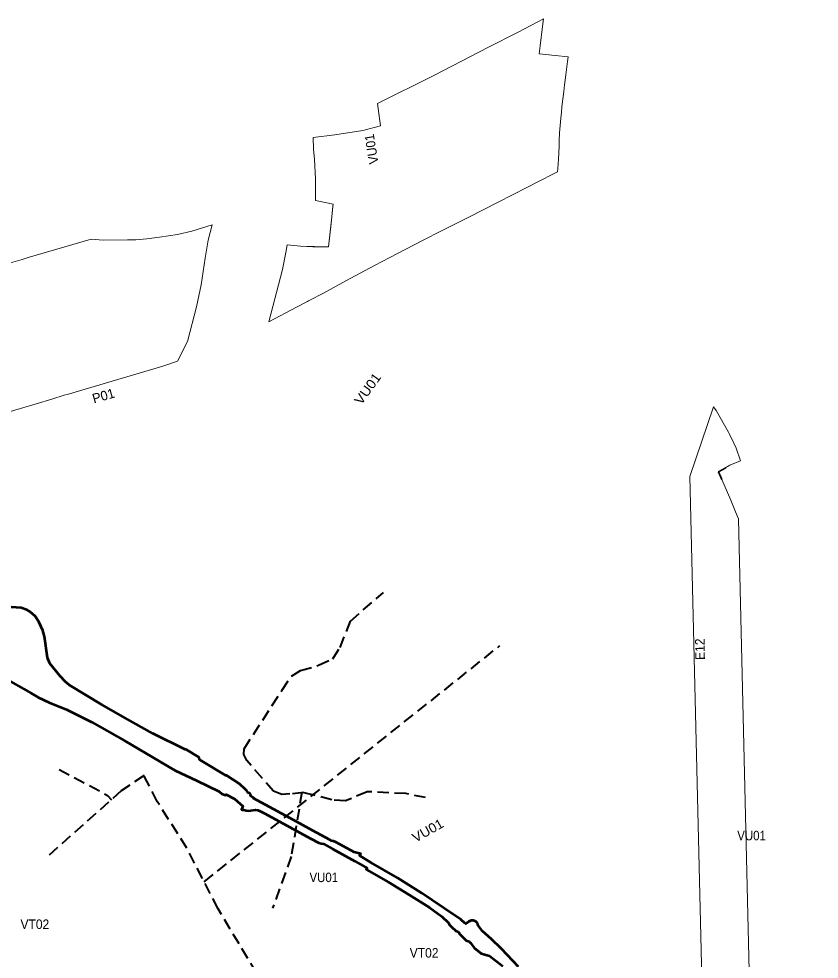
# Model space of a CAD drawing. Extents: x -650145 to -642675, y -1074338 to -1066724.
# Drawn here: x -646512 to -644824, y -1069249 to -1067267 of the extents above; entities that cross this region are included whole.
import ezdxf

# ---------------------------------------------------------------- set-up
doc = ezdxf.new("R2010")
doc.units = 0
doc.header["$LTSCALE"] = 8
doc.linetypes.add('MEDIUM_DASHED', pattern=[4.5, 3, -1.5])
for name, color, linetype, lineweight in [('12', 7, 'MEDIUM_DASHED', 40), ('15', 7, 'Continuous', 13), ('45', 7, 'Continuous', 53)]:
    doc.layers.add(name, color=color, linetype=linetype, lineweight=lineweight)
doc.layers.add('17', color=7, linetype='Continuous')
doc.layers.add('2', color=7, linetype='Continuous')

msp = doc.modelspace()

# ---------------------------------------------------------------- linework, layer by layer
at = {"layer": '12'}
msp.add_line((-646121.289, -1069086.031), (-645497.437, -1068588.325), dxfattribs=at)
for points in [[(-645654.382, -1068908.587), (-645695.934, -1068900.379), (-645777.633, -1068896.262), (-645823.286, -1068915.717), (-645852.103, -1068913.393), (-645911.131, -1068898.055), (-645940.704, -1068901.002), (-645957.145, -1068902.238), (-645974.835, -1068895.314), (-646031.512, -1068830.196), (-646037.554, -1068818.111), (-646037.089, -1068805.562), (-645957.124, -1068682.702), (-645937.201, -1068653.001), (-645917.947, -1068640.958), (-645880.242, -1068629.719), (-645849.757, -1068616.071), (-645834.514, -1068591.986), (-645812.854, -1068536.591), (-645743.059, -1068476.379)], [(-646426.669, -1068849.138), (-646325.196, -1068903.916), (-646316.818, -1068913.099)], [(-646062.183, -1069574.695), (-646024.736, -1069561.612), (-645973.562, -1069340.254), (-646092.013, -1069143.037), (-646157.557, -1069015.41), (-646220.085, -1068916.892), (-646248.016, -1068862.258), (-646295.932, -1068894.5), (-646451.322, -1069032.874)], [(-645915.285, -1068897.386), (-645937.63, -1069033.023), (-645976.999, -1069141.866)]]:
    msp.add_lwpolyline(points, dxfattribs=at)
at = {"layer": '15'}
for points in [[(-645405.461, -1067266.956), (-645459.124, -1067294.842), (-645523.1, -1067327.464), (-645578.654, -1067356.15), (-645636.938, -1067386.16), (-645755.627, -1067445.619), (-645754.45, -1067456.07), (-645749.67, -1067492.54), (-645786.52, -1067502.4), (-645845.49, -1067511.66), (-645891.61, -1067517.46), (-645890.8, -1067542.09), (-645888.69, -1067563.35), (-645886.5, -1067604.41), (-645886.3, -1067638)], [(-645353.76, -1067347.31), (-645381.01, -1067344.47), (-645414.55, -1067340.98), (-645412.77, -1067323.6), (-645407.69, -1067283.25), (-645405.461, -1067266.956)], [(-645360.9, -1067401.05), (-645358.77, -1067385.3), (-645356.48, -1067368.37), (-645354.97, -1067357.16), (-645353.76, -1067347.31)], [(-645366.91, -1067452.72), (-645363.1, -1067419.95), (-645361.48, -1067406.06), (-645360.9, -1067401.05)], [(-645369.16, -1067476.7), (-645367.93, -1067463.58), (-645366.91, -1067452.72)], [(-645371.73, -1067507.06), (-645371.09, -1067499.49), (-645369.16, -1067476.7)], [(-645374.09, -1067562.75), (-645373, -1067535.51), (-645372.51, -1067523.27), (-645371.73, -1067507.06)], [(-645376.157, -1067589.286), (-645375.63, -1067582.48), (-645374.09, -1067562.75)], [(-645984.712, -1067905.99), (-645926.226, -1067874.994), (-645903.512, -1067862.929), (-645901.047, -1067861.609), (-645900.008, -1067861.056), (-645869.73, -1067844.967), (-645822.534, -1067819.103), (-645761.702, -1067787.243), (-645713.714, -1067761.995), (-645660.64, -1067734.415), (-645619.713, -1067713.557), (-645563.205, -1067684.762), (-645501.082, -1067653.64), (-645441.166, -1067622.79), (-645386.14, -1067594.376), (-645376.157, -1067589.286)], [(-645886.3, -1067638), (-645886.24, -1067648.47), (-645886.23, -1067649.44), (-645886.23, -1067649.94), (-645849.48, -1067657.36), (-645849.52, -1067657.86), (-645849.92, -1067662.49)], [(-645849.92, -1067662.49), (-645850.48, -1067668.94), (-645851.81, -1067684.35), (-645858.82, -1067747.99), (-645892.22, -1067747.76), (-645917.73, -1067746.17), (-645946.03, -1067743.35), (-645949.27, -1067759.64), (-645955.97, -1067795.26), (-645984.712, -1067905.99)], [(-645917.73, -1067746.17), (-645858.82, -1067747.99), (-645853.346, -1067698.291), (-645849.92, -1067662.49)], [(-646137.4, -1067874.3), (-646127.7, -1067827.4), (-646118.8, -1067771.3), (-646113, -1067733.4), (-646104.6, -1067701), (-646147.4, -1067714.8), (-646177.7, -1067721.6), (-646215.6, -1067727), (-646241.8, -1067731), (-646265.3, -1067733), (-646282.66, -1067733.1), (-646334.1, -1067733.4), (-646359.237, -1067731.258), (-646492.002, -1067769.967)], [(-646492.002, -1067769.967), (-646504.961, -1067774.022), (-646529.365, -1067781.499)], [(-646409.773, -1068058.581), (-646208.581, -1067999.266), (-646177.649, -1067988.892), (-646156.3, -1067947.3), (-646137.4, -1067874.3)], [(-646574, -1068107.461), (-646508.21, -1068088.256), (-646442.535, -1068068.661), (-646416.219, -1068060.598), (-646409.773, -1068058.581)], [(-645047.446, -1068085.007), (-645096.974, -1068231.922), (-645065.08, -1069583.124), (-644926.299, -1070334.854)], [(-644958.761, -1070986.696), (-644824.411, -1070335.926), (-644965.296, -1069572.802), (-644994.849, -1068320.753), (-645000.93, -1068306.11), (-645010.65, -1068282), (-645036.69, -1068221.92), (-645012.64, -1068208.23), (-644990.43, -1068198.75), (-644999.74, -1068171.88), (-645004.64, -1068161.3), (-645014.09, -1068140.85), (-645015.38, -1068138.59), (-645041.75, -1068092.48), (-645047.446, -1068085.007)]]:
    msp.add_lwpolyline(points, dxfattribs=at)
at = {"layer": '15', "lineweight": 35}
msp.add_lwpolyline([(-645029.39, -1068238.047), (-645036.69, -1068221.92), (-645021.142, -1068213.582)], dxfattribs=at)
at = {"layer": '45'}
for points in [[(-645458.45, -1069265.56), (-645494.13, -1069227.63), (-645515.89, -1069206.66), (-645534.25, -1069190.56), (-645543.43, -1069178.39), (-645544.154, -1069175.682), (-645544.448, -1069174.993), (-645545.631, -1069172.966), (-645547.269, -1069171.107), (-645548.594, -1069170.034), (-645550.076, -1069169.141), (-645551.674, -1069168.459), (-645553.344, -1069168.007), (-645555.036, -1069167.793), (-645556.702, -1069167.808), (-645558.298, -1069168.035), (-645559.793, -1069168.445), (-645561.162, -1069169.007), (-645561.794, -1069169.334), (-645562.95, -1069170.06), (-645567.5, -1069173.46), (-645569.81, -1069175.03), (-645571.9, -1069173.43), (-645579.94, -1069165.52), (-645616.63, -1069140.8), (-645662.44, -1069109.89), (-645694.447, -1069089.98), (-645713.61, -1069078.06), (-645770.04, -1069045.34), (-645773.38, -1069043.46), (-645793.638, -1069031.021), (-645790.53, -1069027.19), (-645805.16, -1069023.52), (-645843.56, -1069002.41), (-645848.18, -1069000.48), (-645852.91, -1068999.62), (-645856.26, -1068997.79), (-645892.77, -1068977.86), (-645933.28, -1068955.74), (-645975.31, -1068932.8), (-646017.55, -1068909.75), (-646017.39, -1068908.42), (-646023.56, -1068905.05), (-646023.13, -1068903.12), (-646023.92, -1068900.73), (-646025.57, -1068899.39), (-646028.18, -1068898.89), (-646031.31, -1068894.32), (-646034.65, -1068891.12), (-646046.48, -1068879.92), (-646074.78, -1068861.51), (-646075.56, -1068861.95), (-646130.68, -1068829.21), (-646132.62, -1068823.54), (-646159.1, -1068807.43), (-646161.45, -1068807.54), (-646229.44, -1068773.53), (-646288.59, -1068740.88), (-646331.26, -1068716.25), (-646337.93, -1068712.4), (-646404.83, -1068671.52), (-646413.45, -1068664.71), (-646425.11, -1068652.37), (-646446.54, -1068626.14), (-646451.82, -1068614.31), (-646458.03, -1068569.26), (-646461.14, -1068556.34), (-646469.51, -1068538.15), (-646477.41, -1068526.45), (-646487.92, -1068516.87), (-646495.416, -1068512.888), (-646507.4, -1068508.45), (-646528.18, -1068507.58)], [(-646545.73, -1068654.81), (-646486.23, -1068688.54), (-646470.225, -1068697.579), (-646448.02, -1068707.99), (-646411.3, -1068723.11), (-646357.87, -1068749.64), (-646288.37, -1068789.04), (-646214.92, -1068832.85), (-646195.52, -1068843.92), (-646182.57, -1068851.3), (-646137.23, -1068872.6), (-646089.63, -1068895.5), (-646084.1, -1068900.51), (-646076.09, -1068903.48), (-646074.51, -1068901.9), (-646057.13, -1068911.62), (-646039.84, -1068926.67), (-646042.5, -1068933.91), (-646040.65, -1068934.59), (-646037.5, -1068934.7), (-646032.61, -1068936.1), (-646027.69, -1068936.6), (-646022.77, -1068936.12), (-646017.6, -1068934.89), (-646012.64, -1068934.34), (-646007.7, -1068935.18), (-646002.95, -1068936.95), (-645993.5, -1068942.1), (-645940.77, -1068970.74), (-645896.91, -1068994.75), (-645879.17, -1069004.02), (-645874.49, -1069005.73), (-645869.83, -1069006.45), (-645850.79, -1069016.84), (-645803.29, -1069042.92), (-645781.12, -1069055.29), (-645777.73, -1069057.2), (-645779.49, -1069059.92), (-645773.29, -1069063.99), (-645732.65, -1069086.82), (-645688.87, -1069113.44), (-645646.08, -1069140.37), (-645620.2, -1069159.26), (-645606.11, -1069172.98), (-645603.91, -1069176.86), (-645599, -1069181.48), (-645590.41, -1069189.45), (-645584.73, -1069191.88), (-645582.63, -1069195.88), (-645568.9, -1069209.87), (-645562.17, -1069212.02), (-645560.72, -1069214.25), (-645559.33, -1069214.54), (-645552.2, -1069225.59), (-645537.44, -1069237.41), (-645519.59, -1069242.38), (-645491.63, -1069264.25)]]:
    msp.add_lwpolyline(points, dxfattribs=at)

# ---------------------------------------------------------------- texts
at = {"layer": '17'}
msp.add_text('P01', height=20, rotation=15.899, dxfattribs=at).set_placement((-646353.668, -1068077.79))
at = {"layer": '17', "width": 0.95}
msp.add_text('E12', height=20, rotation=90.939, dxfattribs=at).set_placement((-645065.46, -1068618.338))
for p in [(-646508.55, -1069185.576), (-645687.853, -1069245.943)]:
    msp.add_text('VT02', height=20, dxfattribs=at).set_placement(p)
at = {"layer": '2'}
for rotation, width, p in [(99.44, 0.95, (-645753.336, -1067571.35)), (54.217, 1.1, (-645789.911, -1068082.457)), (29.327, 1.05, (-645675.485, -1069004.004))]:
    msp.add_text('VU01', height=20, rotation=rotation, dxfattribs=dict(at, width=width)).set_placement(p)
at = {"layer": '2', "width": 0.9}
for p in [(-644997.156, -1068998.703), (-645899.102, -1069086.768)]:
    msp.add_text('VU01', height=20, dxfattribs=at).set_placement(p)

doc.saveas('drawing.dxf')
